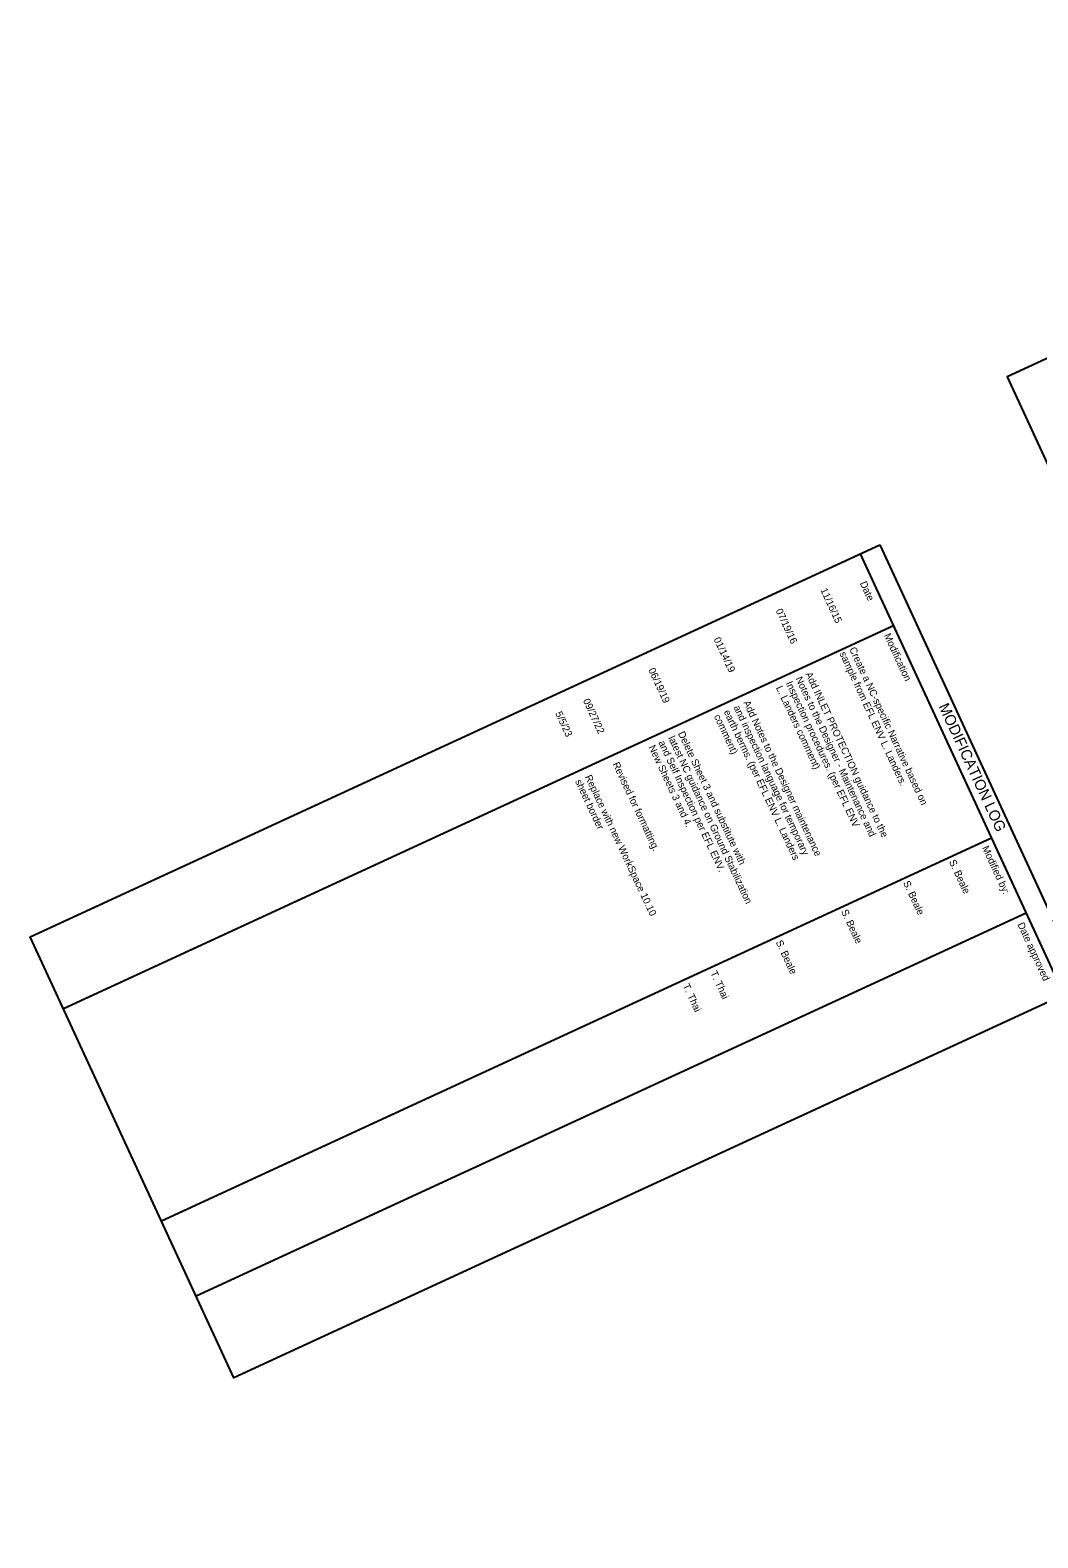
# Model space of a CAD drawing. Extents: x 3013707 to 3016392, y 780251 to 783867.
# Drawn here: x 3013707 to 3014242, y 783065 to 783867 of the extents above; entities that cross this region are included whole.
import ezdxf

# ---------------------------------------------------------------- set-up
doc = ezdxf.new("R2010")
doc.units = 0
doc.layers.add('D_Plot_Shape', color=7, linetype='Continuous')
doc.layers.add('D_Tables', color=7, linetype='Continuous')

msp = doc.modelspace()

# ---------------------------------------------------------------- linework, layer by layer
at = {"layer": 'D_Plot_Shape'}
msp.add_lwpolyline([(3014910.7, 783249.75), (3014625.66, 783867.13), (3014226.18, 783682.69), (3014511.22, 783065.31)], close=True, dxfattribs=at)
at = {"layer": 'D_Tables'}
for p, q in [((3014148, 783588.54), (3014256.21, 783354.02)), ((3014165.63, 783550.32), (3013724.39, 783346.71)), ((3014217.74, 783437.4), (3013776.5, 783233.79)), ((3014236.17, 783397.45), (3013794.94, 783193.84))]:
    msp.add_line(p, q, dxfattribs=at)
msp.add_lwpolyline([(3014158.42, 783593.35), (3014266.64, 783358.83), (3013814.98, 783150.41), (3013706.76, 783384.93)], close=True, dxfattribs=at)

# ---------------------------------------------------------------- texts
for s, height, rotation, p in [('11/16/15', 3.829, 294.77125, (3014126.73, 783569.42)), ('Date', 3.829, 294.77125, (3014147.72, 783573)), ('07/19/16', 3.829, 294.77125, (3014102.96, 783558.44)), ('Modification', 3.8289, 294.77125, (3014160.52, 783545.27)), ('01/14/19', 3.829, 294.77125, (3014070, 783543.23)), ('Create a NC-specific Narrative based on', 3.8289, 294.77125, (3014142.08, 783538.02)), ('sample from EFL ENV L. Landers.', 3.8289, 294.77125, (3014136.87, 783535.61)), ('06/19/19', 3.829, 294.77125, (3014035.25, 783526.9)), ('Notes to the Designer - Maintenance and', 3.8289, 295.11484, (3014113.52, 783522.28)), ('Add INLET PROTECTION guidance to the', 3.8289, 295.11484, (3014118.72, 783524.72)), ('L. Landers comment)', 3.8289, 295.11484, (3014103.12, 783517.4)), ('Inspection procedures. (per EFL ENV ', 3.8289, 295.11484, (3014108.32, 783519.84)), ('09/27/22', 3.829, 294.77125, (3014000.51, 783510.57)), ('earth berms. (per EFL ENV L. Landers', 3.8289, 295.11484, (3014075.36, 783504.62)), ('and inspection language for temporary', 3.8289, 295.11484, (3014080.56, 783507.06)), ('Add Notes to the Designer maintenance', 3.8289, 295.11484, (3014085.76, 783509.5)), ('MODIFICATION LOG', 5.7433, 294.77125, (3014189.52, 783507.56)), ('5/5/23', 3.829, 294.77125, (3013985.79, 783503.77)), ('comment)', 3.829, 295.11484, (3014070.16, 783502.18)), ('latest NC guidance on Ground Stabilization', 3.8289, 295.11484, (3014045.82, 783490.73)), ('Delete Sheet 3 and substitute with ', 3.8289, 295.11484, (3014051.02, 783493.17)), ('New Sheets 3 and 4.', 3.8289, 295.11484, (3014035.41, 783485.85)), ('and Self Inspection per EFL ENV.', 3.8289, 295.11484, (3014040.62, 783488.29)), ('Revised for formatting.', 3.8289, 295.11484, (3014016.27, 783476.84)), ('sheet border', 3.8289, 295.11484, (3013996.35, 783467.61)), ('Replace with new WorkSpace 10.10', 3.8289, 295.11484, (3014001.55, 783470.04)), ('Modified by:', 3.8289, 294.77125, (3014212.66, 783432.28)), ('S. Beale', 3.829, 294.77125, (3014195.11, 783424.97)), ('S. Beale', 3.829, 294.77125, (3014170.71, 783413.71)), ('S. Beale', 3.829, 294.77125, (3014137.75, 783398.49)), ('Date approved', 3.8289, 294.77125, (3014231.45, 783391.56)), ('S. Beale', 3.829, 294.77125, (3014103, 783382.16)), ('T. Thai', 3.829, 294.77125, (3014068.25, 783365.83)), ('T. Thai', 3.829, 294.77125, (3014053.54, 783359.03))]:
    msp.add_text(s, height=height, rotation=rotation, dxfattribs=at).set_placement(p)

doc.saveas('drawing.dxf')
